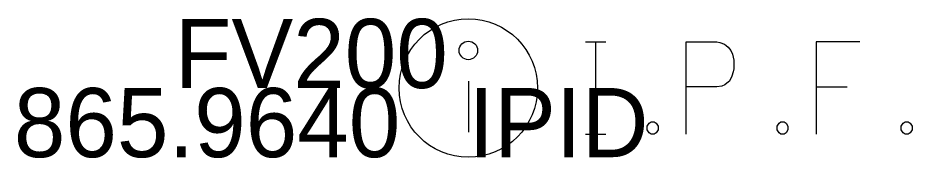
# Model space of a CAD drawing. Extents: x 1479425 to 1480294, y 379351 to 380102.
# Drawn here: x 1479917.567 to 1479918.341, y 379924.285 to 379924.407 of the extents above; entities that cross this region are included whole.
import ezdxf

# ---------------------------------------------------------------- set-up
doc = ezdxf.new("R2010")
doc.units = 0
for name, color, linetype in [('SV_X_Mon_Cells_Found', 7, 'Continuous'), ('SV_X_Text_Comment', 7, 'Continuous'), ('SV_X_Text_Elevation', 7, 'Continuous'), ('SV_X_Text_Name', 7, 'Continuous')]:
    doc.layers.add(name, color=color, linetype=linetype)

msp = doc.modelspace()

# ---------------------------------------------------------------- linework, layer by layer
at = {"layer": 'SV_X_Mon_Cells_Found'}
msp.add_line((1479917.957, 379924.35215), (1479917.957, 379924.30799), dxfattribs=at)
for points in [[(1479918.05851, 379924.38632), (1479918.07615, 379924.38632)], [(1479918.06733, 379924.30632), (1479918.06733, 379924.38632)], [(1479918.1456, 379924.30632), (1479918.1456, 379924.38632), (1479918.17205, 379924.38632), (1479918.17481, 379924.38568), (1479918.17866, 379924.38442), (1479918.18032, 379924.38317), (1479918.18197, 379924.38191), (1479918.18418, 379924.37876), (1479918.18583, 379924.37561), (1479918.18694, 379924.37057), (1479918.18694, 379924.36301), (1479918.18638, 379924.36049), (1479918.18528, 379924.35671), (1479918.18307, 379924.35231), (1479918.18087, 379924.35041), (1479918.17922, 379924.34915), (1479918.17646, 379924.34789), (1479918.17205, 379924.34727), (1479918.1456, 379924.34727)], [(1479918.29606, 379924.38632), (1479918.25803, 379924.38632), (1479918.25803, 379924.30632)], [(1479918.25803, 379924.34727), (1479918.28504, 379924.34727)], [(1479918.11529, 379924.31703), (1479918.11804, 379924.31703), (1479918.1197, 379924.31577), (1479918.12134, 379924.31325), (1479918.12134, 379924.3101), (1479918.1197, 379924.30758), (1479918.11804, 379924.30632), (1479918.11529, 379924.30632), (1479918.11363, 379924.30758), (1479918.11198, 379924.3101), (1479918.11198, 379924.31325), (1479918.11363, 379924.31577), (1479918.11529, 379924.31703)], [(1479918.22772, 379924.31703), (1479918.23047, 379924.31703), (1479918.23213, 379924.31577), (1479918.23378, 379924.31325), (1479918.23378, 379924.3101), (1479918.23213, 379924.30758), (1479918.23047, 379924.30632), (1479918.22772, 379924.30632), (1479918.22606, 379924.30758), (1479918.22441, 379924.3101), (1479918.22441, 379924.31325), (1479918.22606, 379924.31577), (1479918.22772, 379924.31703)], [(1479918.33519, 379924.31703), (1479918.33794, 379924.31703), (1479918.3396, 379924.31577), (1479918.34125, 379924.31325), (1479918.34125, 379924.3101), (1479918.3396, 379924.30758), (1479918.33794, 379924.30632), (1479918.33519, 379924.30632), (1479918.33353, 379924.30758), (1479918.33188, 379924.3101), (1479918.33188, 379924.31325), (1479918.33353, 379924.31577), (1479918.33519, 379924.31703)], [(1479918.05851, 379924.30632), (1479918.07615, 379924.30632)]]:
    msp.add_lwpolyline(points, dxfattribs=at)
for centre, radius in [((1479917.957, 379924.34632), 0.06), ((1479917.957, 379924.3789), 0.008)]:
    msp.add_circle(centre, radius, dxfattribs=at)

# ---------------------------------------------------------------- texts
at = {"layer": 'SV_X_Text_Comment'}
msp.add_text('IPID', height=0.06, dxfattribs=at).set_placement((1479917.957, 379924.28632))
at = {"layer": 'SV_X_Text_Elevation'}
msp.add_text('865.9640', height=0.06, dxfattribs=at).set_placement((1479917.56348, 379924.28632))
at = {"layer": 'SV_X_Text_Name'}
msp.add_text('FV200', height=0.06, dxfattribs=at).set_placement((1479917.70285, 379924.34632))

doc.saveas('drawing.dxf')
